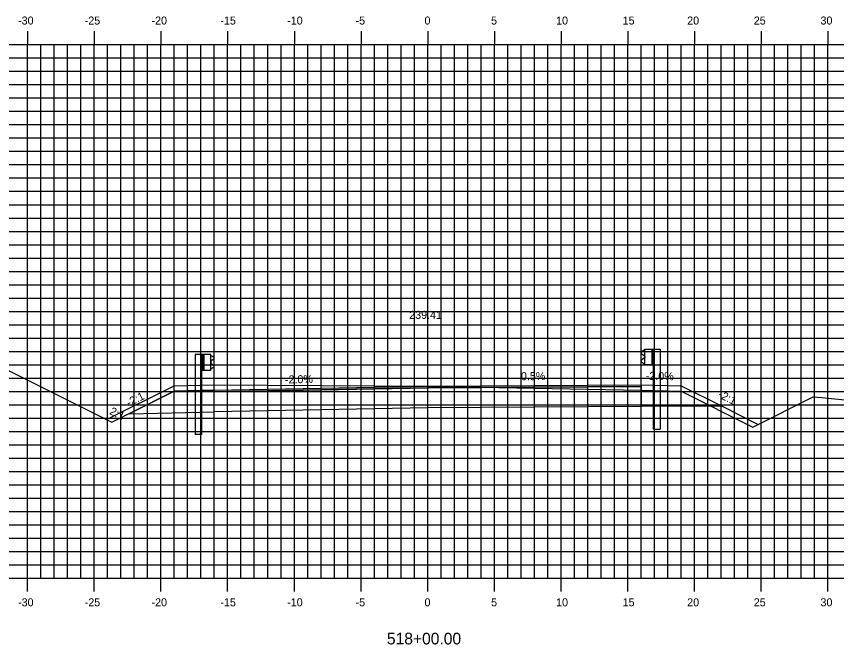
# Model space of a CAD drawing. Extents: x 1170543 to 1177585, y 609599 to 610623.
# Drawn here: x 1174143.7 to 1174205.2, y 610272.8 to 610319.9 of the extents above; entities that cross this region are included whole.
import ezdxf

# ---------------------------------------------------------------- set-up
doc = ezdxf.new("R2010")
doc.units = 0
for name, color, linetype in [('ANNOTATION', 7, 'Continuous'), ('D_Guardrail_Beam_Lt', 7, 'Continuous'), ('D_Guardrail_Beam_Rt', 7, 'Continuous'), ('D_Roadway_Centerline', 7, 'Continuous'), ('D_Roadway_Centerline_Text', 7, 'Continuous'), ('D_Roadway_Edge_Shoulder', 7, 'Continuous'), ('D_Roadway_Edge_TW', 7, 'Continuous'), ('D_Roadway_Pavement', 7, 'Continuous'), ('D_Roadway_SubGrade', 7, 'Continuous'), ('H_V ANNOTATION', 7, 'Continuous'), ('MAJOR', 7, 'Continuous'), ('MINOR', 7, 'Continuous'), ('S_Roadway_Centerline', 7, 'Continuous')]:
    doc.layers.add(name, color=color, linetype=linetype)

msp = doc.modelspace()

# ---------------------------------------------------------------- linework, layer by layer
at = {"layer": 'D_Guardrail_Beam_Lt'}
for p, q in [((1174157.147, 610294.576), (1174157.147, 610288.576)), ((1174157.618, 610294.576), (1174157.147, 610294.576)), ((1174158.305, 610294.576), (1174157.618, 610294.576)), ((1174157.618, 610294.576), (1174157.618, 610293.41)), ((1174157.68, 610294.576), (1174157.68, 610293.41)), ((1174157.784, 610294.576), (1174157.784, 610293.41)), ((1174158.305, 610293.41), (1174158.305, 610294.576)), ((1174158.305, 610294.493), (1174158.379, 610294.479)), ((1174158.395, 610294.472), (1174158.539, 610294.372)), ((1174158.309, 610294.028), (1174158.309, 610293.958)), ((1174158.539, 610294.229), (1174158.343, 610294.093)), ((1174158.343, 610293.894), (1174158.539, 610293.757)), ((1174157.618, 610293.41), (1174158.305, 610293.41)), ((1174157.638, 610288.576), (1174157.638, 610293.41)), ((1174158.379, 610293.508), (1174158.305, 610293.493)), ((1174158.539, 610293.614), (1174158.395, 610293.514)), ((1174157.638, 610288.576), (1174157.147, 610288.576))]:
    msp.add_line(p, q, dxfattribs=at)
for centre, major_axis, start_param, end_param in [((1174158.371, 610294.438), (0.0417, 0), 0.959931, 1.376053), ((1174158.388, 610294.028), (-0.0789, 0), 5.323254, 6.283185), ((1174158.388, 610293.958), (-0.0789, 0), 6.283185, 7.243116), ((1174158.488, 610294.3), (0.0877, 0), 5.323254, 7.243116), ((1174158.371, 610293.548), (0.0417, 0), 4.907132, 5.323254), ((1174158.488, 610293.686), (0.0877, 0), 5.323254, 7.243116)]:
    msp.add_ellipse(centre, major_axis=major_axis, ratio=0.995501, start_param=start_param, end_param=end_param, dxfattribs=at)
at = {"layer": 'D_Guardrail_Beam_Rt'}
for p, q in [((1174190.757, 610294.869), (1174190.613, 610294.769)), ((1174190.613, 610294.626), (1174190.809, 610294.49)), ((1174190.847, 610294.89), (1174190.773, 610294.876)), ((1174190.842, 610294.425), (1174190.842, 610294.355)), ((1174190.847, 610294.974), (1174191.534, 610294.974)), ((1174190.847, 610293.807), (1174190.847, 610294.974)), ((1174191.368, 610294.974), (1174191.368, 610293.807)), ((1174191.472, 610294.974), (1174191.472, 610293.807)), ((1174191.534, 610294.974), (1174192.005, 610294.974)), ((1174191.534, 610294.974), (1174191.534, 610293.807)), ((1174192.005, 610294.974), (1174192.005, 610288.974)), ((1174190.809, 610294.291), (1174190.613, 610294.155)), ((1174190.613, 610294.012), (1174190.757, 610293.912)), ((1174190.773, 610293.905), (1174190.847, 610293.89)), ((1174191.534, 610293.807), (1174190.847, 610293.807)), ((1174191.513, 610288.974), (1174191.513, 610293.807)), ((1174191.513, 610288.974), (1174192.005, 610288.974))]:
    msp.add_line(p, q, dxfattribs=at)
for centre, major_axis, start_param, end_param in [((1174190.664, 610294.698), (-0.0877, 0), 5.323254, 7.243116), ((1174190.781, 610294.835), (-0.0417, 0), 4.907132, 5.323254), ((1174190.763, 610294.425), (0.0789, 0), 0, 0.959931), ((1174190.664, 610294.083), (-0.0877, 0), 5.323254, 7.243116), ((1174190.781, 610293.946), (-0.0417, 0), 0.959931, 1.376053), ((1174190.763, 610294.355), (0.0789, 0), 5.323254, 6.283185)]:
    msp.add_ellipse(centre, major_axis=major_axis, ratio=0.995501, start_param=start_param, end_param=end_param, dxfattribs=at)
at = {"layer": 'D_Roadway_Centerline'}
msp.add_lwpolyline([(1174150.504, 610289.691), (1174150.9, 610289.493), (1174155.576, 610291.831), (1174158.576, 610291.891), (1174174.576, 610292.211), (1174190.576, 610292.288), (1174193.576, 610292.228), (1174196.647, 610290.692), (1174199.36, 610289.336)], dxfattribs=at)
at = {"layer": 'D_Roadway_Edge_Shoulder'}
for points in [[(1174190.576, 610292.288), (1174190.576, 610292.163)], [(1174158.576, 610291.891), (1174158.576, 610291.766)]]:
    msp.add_lwpolyline(points, dxfattribs=at)
at = {"layer": 'D_Roadway_Edge_TW'}
msp.add_lwpolyline([(1174158.576, 610291.766), (1174158.576, 610291.891), (1174174.576, 610292.211), (1174190.576, 610292.288), (1174190.576, 610292.163), (1174174.576, 610292.086)], close=True, dxfattribs=at)
at = {"layer": 'D_Roadway_Pavement'}
msp.add_lwpolyline([(1174158.576, 610291.766), (1174158.576, 610291.766), (1174174.576, 610292.086), (1174190.576, 610292.163), (1174190.576, 610292.163), (1174174.576, 610292.086)], close=True, dxfattribs=at)
for points in [[(1174190.576, 610292.163), (1174190.576, 610292.163)], [(1174190.576, 610292.163), (1174190.576, 610292.163)], [(1174158.576, 610291.766), (1174158.576, 610291.766)], [(1174158.576, 610291.766), (1174158.576, 610291.766)]]:
    msp.add_lwpolyline(points, dxfattribs=at)
at = {"layer": 'D_Roadway_SubGrade'}
for points in [[(1174158.576, 610290.266), (1174158.576, 610291.766), (1174174.576, 610292.086), (1174190.576, 610292.163), (1174190.576, 610290.663), (1174174.576, 610290.586)], [(1174190.576, 610292.288), (1174193.576, 610292.228), (1174196.647, 610290.692), (1174190.576, 610290.663)], [(1174158.576, 610291.891), (1174155.576, 610291.831), (1174152.19, 610290.138), (1174158.576, 610290.266)]]:
    msp.add_lwpolyline(points, close=True, dxfattribs=at)
at = {"layer": 'MAJOR'}
for p, q in [((1174144.576, 610318.803), (1174144.576, 610317.801)), ((1174149.576, 610318.803), (1174149.576, 610317.801)), ((1174154.576, 610318.803), (1174154.576, 610317.801)), ((1174159.576, 610318.803), (1174159.576, 610317.801)), ((1174164.576, 610318.803), (1174164.576, 610317.801)), ((1174169.576, 610318.803), (1174169.576, 610317.801)), ((1174174.576, 610318.803), (1174174.576, 610317.801)), ((1174179.576, 610318.803), (1174179.576, 610317.801)), ((1174184.576, 610318.803), (1174184.576, 610317.801)), ((1174189.576, 610318.803), (1174189.576, 610317.801)), ((1174194.576, 610318.803), (1174194.576, 610317.801)), ((1174199.576, 610318.803), (1174199.576, 610317.801)), ((1174204.576, 610318.803), (1174204.576, 610317.801)), ((1174104.576, 610317.801), (1174244.576, 610317.801)), ((1174104.576, 610317.801), (1174244.576, 610317.801)), ((1174144.576, 610277.801), (1174144.576, 610317.801)), ((1174149.576, 610277.801), (1174149.576, 610317.801)), ((1174154.576, 610277.801), (1174154.576, 610317.801)), ((1174159.576, 610277.801), (1174159.576, 610317.801)), ((1174164.576, 610277.801), (1174164.576, 610317.801)), ((1174169.576, 610277.801), (1174169.576, 610317.801)), ((1174174.576, 610277.801), (1174174.576, 610317.801)), ((1174179.576, 610277.801), (1174179.576, 610317.801)), ((1174184.576, 610277.801), (1174184.576, 610317.801)), ((1174189.576, 610277.801), (1174189.576, 610317.801)), ((1174194.576, 610277.801), (1174194.576, 610317.801)), ((1174199.576, 610277.801), (1174199.576, 610317.801)), ((1174204.576, 610277.801), (1174204.576, 610317.801)), ((1174104.576, 610312.801), (1174244.576, 610312.801)), ((1174104.576, 610307.801), (1174244.576, 610307.801)), ((1174104.576, 610302.801), (1174244.576, 610302.801)), ((1174104.576, 610297.801), (1174244.576, 610297.801)), ((1174104.576, 610292.801), (1174244.576, 610292.801)), ((1174104.576, 610287.801), (1174244.576, 610287.801)), ((1174104.576, 610282.801), (1174244.576, 610282.801)), ((1174104.576, 610277.801), (1174244.576, 610277.801)), ((1174104.576, 610277.801), (1174244.576, 610277.801)), ((1174144.576, 610276.799), (1174144.576, 610277.801)), ((1174149.576, 610276.799), (1174149.576, 610277.801)), ((1174154.576, 610276.799), (1174154.576, 610277.801)), ((1174159.576, 610276.799), (1174159.576, 610277.801)), ((1174164.576, 610276.799), (1174164.576, 610277.801)), ((1174169.576, 610276.799), (1174169.576, 610277.801)), ((1174174.576, 610276.799), (1174174.576, 610277.801)), ((1174179.576, 610276.799), (1174179.576, 610277.801)), ((1174184.576, 610276.799), (1174184.576, 610277.801)), ((1174189.576, 610276.799), (1174189.576, 610277.801)), ((1174194.576, 610276.799), (1174194.576, 610277.801)), ((1174199.576, 610276.799), (1174199.576, 610277.801)), ((1174204.576, 610276.799), (1174204.576, 610277.801))]:
    msp.add_line(p, q, dxfattribs=at)
at = {"layer": 'MINOR'}
for p, q in [((1174145.576, 610277.801), (1174145.576, 610317.801)), ((1174146.576, 610277.801), (1174146.576, 610317.801)), ((1174147.576, 610277.801), (1174147.576, 610317.801)), ((1174148.576, 610277.801), (1174148.576, 610317.801)), ((1174150.576, 610277.801), (1174150.576, 610317.801)), ((1174151.576, 610277.801), (1174151.576, 610317.801)), ((1174152.576, 610277.801), (1174152.576, 610317.801)), ((1174153.576, 610277.801), (1174153.576, 610317.801)), ((1174155.576, 610277.801), (1174155.576, 610317.801)), ((1174156.576, 610277.801), (1174156.576, 610317.801)), ((1174157.576, 610277.801), (1174157.576, 610317.801)), ((1174158.576, 610277.801), (1174158.576, 610317.801)), ((1174160.576, 610277.801), (1174160.576, 610317.801)), ((1174161.576, 610277.801), (1174161.576, 610317.801)), ((1174162.576, 610277.801), (1174162.576, 610317.801)), ((1174163.576, 610277.801), (1174163.576, 610317.801)), ((1174165.576, 610277.801), (1174165.576, 610317.801)), ((1174166.576, 610277.801), (1174166.576, 610317.801)), ((1174167.576, 610277.801), (1174167.576, 610317.801)), ((1174168.576, 610277.801), (1174168.576, 610317.801)), ((1174170.576, 610277.801), (1174170.576, 610317.801)), ((1174171.576, 610277.801), (1174171.576, 610317.801)), ((1174172.576, 610277.801), (1174172.576, 610317.801)), ((1174173.576, 610277.801), (1174173.576, 610317.801)), ((1174175.576, 610277.801), (1174175.576, 610317.801)), ((1174176.576, 610277.801), (1174176.576, 610317.801)), ((1174177.576, 610277.801), (1174177.576, 610317.801)), ((1174178.576, 610277.801), (1174178.576, 610317.801)), ((1174180.576, 610277.801), (1174180.576, 610317.801)), ((1174181.576, 610277.801), (1174181.576, 610317.801)), ((1174182.576, 610277.801), (1174182.576, 610317.801)), ((1174183.576, 610277.801), (1174183.576, 610317.801)), ((1174185.576, 610277.801), (1174185.576, 610317.801)), ((1174186.576, 610277.801), (1174186.576, 610317.801)), ((1174187.576, 610277.801), (1174187.576, 610317.801)), ((1174188.576, 610277.801), (1174188.576, 610317.801)), ((1174190.576, 610277.801), (1174190.576, 610317.801)), ((1174191.576, 610277.801), (1174191.576, 610317.801)), ((1174192.576, 610277.801), (1174192.576, 610317.801)), ((1174193.576, 610277.801), (1174193.576, 610317.801)), ((1174195.576, 610277.801), (1174195.576, 610317.801)), ((1174196.576, 610277.801), (1174196.576, 610317.801)), ((1174197.576, 610277.801), (1174197.576, 610317.801)), ((1174198.576, 610277.801), (1174198.576, 610317.801)), ((1174200.576, 610277.801), (1174200.576, 610317.801)), ((1174201.576, 610277.801), (1174201.576, 610317.801)), ((1174202.576, 610277.801), (1174202.576, 610317.801)), ((1174203.576, 610277.801), (1174203.576, 610317.801)), ((1174104.576, 610316.801), (1174244.576, 610316.801)), ((1174104.576, 610315.801), (1174244.576, 610315.801)), ((1174104.576, 610314.801), (1174244.576, 610314.801)), ((1174104.576, 610313.801), (1174244.576, 610313.801)), ((1174104.576, 610311.801), (1174244.576, 610311.801)), ((1174104.576, 610310.801), (1174244.576, 610310.801)), ((1174104.576, 610309.801), (1174244.576, 610309.801)), ((1174104.576, 610308.801), (1174244.576, 610308.801)), ((1174104.576, 610306.801), (1174244.576, 610306.801)), ((1174104.576, 610305.801), (1174244.576, 610305.801)), ((1174104.576, 610304.801), (1174244.576, 610304.801)), ((1174104.576, 610303.801), (1174244.576, 610303.801)), ((1174104.576, 610301.801), (1174244.576, 610301.801)), ((1174104.576, 610300.801), (1174244.576, 610300.801)), ((1174104.576, 610299.801), (1174244.576, 610299.801)), ((1174104.576, 610298.801), (1174244.576, 610298.801)), ((1174104.576, 610296.801), (1174244.576, 610296.801)), ((1174104.576, 610295.801), (1174244.576, 610295.801)), ((1174104.576, 610294.801), (1174244.576, 610294.801)), ((1174104.576, 610293.801), (1174244.576, 610293.801)), ((1174104.576, 610291.801), (1174244.576, 610291.801)), ((1174104.576, 610290.801), (1174244.576, 610290.801)), ((1174104.576, 610289.801), (1174244.576, 610289.801)), ((1174104.576, 610288.801), (1174244.576, 610288.801)), ((1174104.576, 610286.801), (1174244.576, 610286.801)), ((1174104.576, 610285.801), (1174244.576, 610285.801)), ((1174104.576, 610284.801), (1174244.576, 610284.801)), ((1174104.576, 610283.801), (1174244.576, 610283.801)), ((1174104.576, 610281.801), (1174244.576, 610281.801)), ((1174104.576, 610280.801), (1174244.576, 610280.801)), ((1174104.576, 610279.801), (1174244.576, 610279.801)), ((1174104.576, 610278.801), (1174244.576, 610278.801))]:
    msp.add_line(p, q, dxfattribs=at)
at = {"layer": 'S_Roadway_Centerline'}
msp.add_lwpolyline([(1174136.231, 610296.828), (1174150.504, 610289.691), (1174150.505, 610289.691), (1174155.576, 610292.227), (1174155.576, 610292.227), (1174155.576, 610292.227), (1174158.576, 610292.287), (1174158.576, 610292.287), (1174174.576, 610292.21), (1174174.576, 610292.21), (1174190.576, 610291.89), (1174193.576, 610291.83), (1174193.576, 610291.83), (1174193.576, 610291.83), (1174198.961, 610289.137), (1174198.961, 610289.137), (1174203.465, 610291.389), (1174203.465, 610291.389), (1174203.465, 610291.389), (1174203.465, 610291.389), (1174203.465, 610291.389), (1174204.112, 610291.348), (1174204.115, 610291.347), (1174213.437, 610290.395)], dxfattribs=at)

# ---------------------------------------------------------------- texts
at = {"layer": 'ANNOTATION'}
for s, rotation, p in [('0.5%', 0.2766, (1174181.565, 610292.645)), ('-2.0%', 358.85424, (1174190.919, 610292.681)), ('-2.0%', 1.14576, (1174163.879, 610292.397)), ('-2:1', 26.56505, (1174152.167, 610290.644)), ('-2:1', 333.43495, (1174196.291, 610291.388)), ('2:1', 333.43495, (1174150.669, 610290.127))]:
    msp.add_text(s, height=0.6, rotation=rotation, dxfattribs=at).set_placement(p)
at = {"layer": 'D_Roadway_Centerline'}
for s, p in [('C', (1174174.571, 610292.211)), ('L', (1174174.576, 610292.203))]:
    msp.add_text(s, height=0.0146, dxfattribs=at).set_placement(p)
at = {"layer": 'D_Roadway_Centerline_Text'}
msp.add_text('239.41', height=0.6, dxfattribs=at).set_placement((1174173.19, 610297.243))
msp.add_text('239.41', height=0.6, dxfattribs=at).set_placement((1174173.19, 610297.243))
at = {"layer": 'H_V ANNOTATION'}
for s, height, p in [('-30', 0.6, (1174143.864, 610319.301)), ('-25', 0.6, (1174148.861, 610319.301)), ('-20', 0.6, (1174153.869, 610319.301)), ('-15', 0.6, (1174159.033, 610319.301)), ('-10', 0.6, (1174164.041, 610319.301)), ('-5', 0.6, (1174169.166, 610319.301)), ('0', 0.6, (1174174.335, 610319.301)), ('5', 0.6, (1174179.327, 610319.301)), ('10', 0.6, (1174184.201, 610319.301)), ('15', 0.6, (1174189.193, 610319.301)), ('20', 0.6, (1174194.03, 610319.301)), ('25', 0.6, (1174199.022, 610319.301)), ('30', 0.6, (1174204.025, 610319.301)), ('-30', 0.6, (1174143.864, 610275.701)), ('-25', 0.6, (1174148.861, 610275.701)), ('-20', 0.6, (1174153.869, 610275.701)), ('-15', 0.6, (1174159.033, 610275.701)), ('-10', 0.6, (1174164.041, 610275.701)), ('-5', 0.6, (1174169.166, 610275.701)), ('0', 0.6, (1174174.335, 610275.701)), ('5', 0.6, (1174179.327, 610275.701)), ('10', 0.6, (1174184.201, 610275.701)), ('15', 0.6, (1174189.193, 610275.701)), ('20', 0.6, (1174194.03, 610275.701)), ('25', 0.6, (1174199.022, 610275.701)), ('30', 0.6, (1174204.025, 610275.701)), ('518+00.00', 0.875, (1174171.517, 610272.844))]:
    msp.add_text(s, height=height, dxfattribs=at).set_placement(p)

doc.saveas('drawing.dxf')
